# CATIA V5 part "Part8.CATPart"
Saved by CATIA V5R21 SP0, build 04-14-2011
Part number: Part1
Bounding box of the stored display mesh (mm): x 0 to 0, y -88 to 173, z -40 to 122.598
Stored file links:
  C:\Users\RIAD MAHAMUD PIASH\Desktop\Part8.CATPart
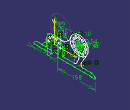
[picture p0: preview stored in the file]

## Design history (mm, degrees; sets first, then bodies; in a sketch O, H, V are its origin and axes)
Body1 (main body)
  Sketch1 on yz-plane, origin (0, 0, 0), H (0, 1, 0), V (0, 0, 1)
    arc A1 centre (0, 0) radius 35 from (35, 0) to (-35, 0) ccw
    point P1 (-35, 0)
    point P2 (35, 0)
    arc A2 centre (0, 0) radius 15 from (15, 0) to (-15, 0) ccw
    point P3 (-15, 0)
    point P4 (15, 0)
    line L1 (-15, 0) -> (-15, -40)
    point P5 (-15, -40)
    line L2 (-35, 0) -> (-35, -26)
    point P6 (-35, -26)
    line L3 (-15, -40) -> (-88, -40)
    line L4 (-35, -26) -> (-74, -26)
    arc A3 centre (-74, -40) radius 14 from (-88, -40) to (-74, -26) cw
    point P10 (15, -40)
    point P11 (15, 0)
    line L5 (15, 0) -> (15, -40)
    point P12 (35, -26)
    point P13 (35, 0)
    line L6 (35, 0) -> (35, -18)
    line L7 (15, -40) -> (173, -40)
    point P15 (106, 50)
    circle A4 centre (106, 50) radius 17
    circle A5 centre (106, 50) radius 10
    construction circle A6 centre (106, 50) radius 27
    axis line L8 (106, 50) -> (106, 96.2385)
    circle A7 centre (106, 77) radius 5
    point P17 (106, 77)
    circle A8 centre (92.5, 73.3827) radius 5
    circle A9 centre (82.6173, 63.5) radius 5
    circle A10 centre (79, 50) radius 5
    circle A11 centre (82.6173, 36.5) radius 5
    circle A12 centre (92.5, 26.6173) radius 5
    circle A13 centre (106, 23) radius 5
    circle A14 centre (120.8322, 23.6993) radius 5
    circle A15 centre (129.3827, 36.5) radius 5
    circle A16 centre (133, 50) radius 5
    circle A17 centre (129.3827, 63.5) radius 5
    circle A18 centre (119.5, 73.3827) radius 5
    circle A19 centre (106, 77) radius 5
    arc A20 centre (26.324, 76.6032) radius 46 from (11.3746, 33.1001) to (69.9561, 62.0348) ccw
    point P32 (11.3746, 33.1001)
    line L9 (123.3205, -26) -> (159, -26)
    line L10 (173, -40) -> (173, -40)
    arc A21 centre (159, -40) radius 14 from (159, -26) to (173, -40) cw
    line L11 (138.909, 31) -> (114.6603, -11)
    point P36 (106, -26)
    arc A22 centre (123.3205, -16) radius 10 from (114.6603, -11) to (123.3205, -26) ccw
    line L12 (43, -26) -> (84.7598, -26)
    line L13 (104.008, -0.8869) -> (95.66, -19.0185)
    point P41 (106, 3.4397)
    point P42 (86, -40)
    arc A23 centre (94.9245, 3.2952) radius 10 from (97.2319, 13.0254) to (104.008, -0.8869) cw
    circle A24 centre (106, 50) radius 38
    point P47 (69.9561, 62.0348)
    arc A25 centre (84.7598, -14) radius 12 from (84.7598, -26) to (95.66, -19.0185) ccw
    circle A26 centre (25, 0) radius 4
    point P51 (25, 0)
    circle A27 centre (20.2254, 14.6946) radius 4
    circle A28 centre (7.7254, 23.7764) radius 4
    circle A29 centre (-7.7254, 23.7764) radius 4
    circle A30 centre (-20.2254, 14.6946) radius 4
    circle A31 centre (-25, 0) radius 4
    circle A32 centre (25, 0) radius 4
    arc A33 centre (43, -18) radius 8 from (43, -26) to (35, -18) cw
    radius A2 = 15
    radius A1 = 35
    length L2 = 26
    length L1 = 40
    length L3 = 73
    length L4 = 39
    radius A3 = 14
    length L7 = 158
    distance P15 V = 106
    distance P15 H = 50
    radius A5 = 10
    radius A4 = 17
    radius A6 = 27
    radius A7 = 5
    radius A20 = 46
    radius A21 = 14
    radius A22 = 10
    distance P42 L8 = 20
    radius A23 = 10
    radius A25 = 12
    radius A26 = 4
    distance P51 L5 = 10
    radius A33 = 8
    coincidence: P1 H, P2 H, P3 H, P4 H, P17 L8, P17 A6, A1 P32, P36 L9, P36 L8, L11 P36, L9 P12, P41 L8, P42 L7, L13 P41, A24 P47, P47 A20, L13 P42, P51 H, L12 P12, L6 P12
    tangency: L1 A2, L2 A1, A20 A1, L9 A3, A21 L9, A21 L10, A22 L11, A22 L9, L12 A22, L13 A14, A23 L13, A24 A20, A25 L12, A25 L13, A33 L12, A33 L6
    horizontal: L3 H, L4 H, L7 H
    symmetry: P5 P10 V, P3 P11 V, L1 L5 V, P6 P12 V, P1 P13 V, L2 L6 V
    vertical: L8 V, L10 V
